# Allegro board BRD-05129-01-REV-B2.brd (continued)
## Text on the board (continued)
DISPLAY_BOTTOM: C369 | C557 | R462 | MH4 | MH3 | J13 | D | C | MH7 | B | 40 | 20 | 60 | U30 | A | 1 | J2 | U28 | R205 | C49 | J6 | J18 | MH10 | J19 | MH6 | J20 | J3 | MH2 | U61 | JA1 | R171 | R173 | R172 | R170 | C110 | C117 | C118 | R206 | C111 | C112 | JA2 | J1 | WATCHDOG OUT | MIO26 | DS1 | DS2 | DS3 | DS4 | DS5 | DS6 | DS7 | DS8 | J17 | SW1 | GND | R45 | J16 | 12V_IN | SW2 | PS_SRST_L | TP3 | C238 | C376 | 11 | 12 | Q5 | C323 | C324 | U41 | C207 | MH5 | TP1 | J12 | C204 | C578 | 2 | C437 | R349 | C275 | R498 | C397 | C396 | C436 | R256 | C577 | C53 | 15 | C303 | C295 | C298 | C296 | C317 | C74 | R62 | R57 | R63 | R61 | R58 | C299 | C291 | C292 | MH9 | R469 | R468 | X6 | C405 | C404 | X5 | C592 | C591 | C530 | C513 | C527 | C514 | U44 | C318 | C274 | C515 | R484 | C529 | C517 | R481 | R482 | R483 | X8 | X7 | C417 | C416 | U46 | MH8 | C546 | C544 | C547 | C545 | C556 | C147 | C166 | C153 | C163 | C159 | R113 | C157 | R461 | J22 | R126 | 59 | J24 | J23 | X10 | C146 | LED1 | DS9 | C156 | C145 | R120 | R108 | R119 | R107 | R118 | R106 | R102 | R125 | R116 | R104 | R105 | R117 | R121 | R109 | DS10 | LED2 | R378 | C481 | C478 | C463 | R397 | C486 | C475 | R402 | C476 | U80 | C472 | R396 | R79 | C427 | C425 | R326 | R380 | R389 | R381 | R390 | R385 | R394 | C465 | C424 | R393 | R384 | R392 | R383 | R391 | R382 | R379 | R401 | C482 | C477 | R330 | R331 | C94 | C426 | R327 | MH11 | MH1 | Q19 | U42 | D1 | J4 | C236 | C565 | C203 | TP39 | C235 | C234 | U82 | TP37 | TP38 | R135 | R133 | C379 | C206 | C377 | C205 | C374 | C372 | C276 | R274 | C370 | C277 | C398 | C394 | Q21 | C392 | C286 | C297 | C285 | R265 | C390 | R296 | C300 | C283 | C388 | C272 | C284 | C525 | C524 | C587 | C589 | C523 | C410 | C520 | C526 | C408 | C588 | C590 | C519 | C516 | C406 | C528 | C518 | C402 | C293 | R306 | C400 | C294 | C422 | C420 | C418 | C414 | R316 | C412 | C164 | C162 | C555 | C160 | C158 | C148 | C152 | C155 | C161 | C144 | C167 | C151 | C165 | U36 | R122 | C149 | R110 | C150 | C154 | C470 | C479 | C468 | R471 | C474 | R472 | C467 | C469 | C464 | C473 | R387 | C87 | L4 | C466 | C471 | C484 | C480 | C483 | L5 | C485 | C96 | C88 | J21 | R235 | J15 | C97 | C93 | MH12 | SOM240_1 | SOM240_2 | J10 | 39 | PCB EDGE | FAN HDR | SOM FPD | CC PS | SOM PL | CC PL | SOM LPD | UF1 | UF2 | PWR IN | PS ETH | SLVS-EC | PL ETH | JTAG | PMOD1 | RESET | FWUEN | 12V PWR | PMOD2 | PMOD3 | PMOD4 | SFP+ | JTAG/UART | RPI GPIO
PLACE_BOUND_BOTTOM: R | U168 | US | C | N | I | Z | E | D | A | 1 | 60 | 40 | 20 | O | G | E115289 | Electrical Safety | 10 | MET | RoHS | D3C386 | JA1 | JA2 | HF
User.8: JA1 | 14 | 1 | A1 | RoHS | U172 | A | 60 | AMD | D3C386 | DE | UL | U144 | D | C | B | 10 | C1767 | C1766 | JA2 | HF
User.10: CLOCK | REGULATOR | 5V0_IN | OSC | USB PHY AND HUB | GATE DRIVERS | MOTOR PHASE | MOTOR VOLTAGE | & CURRENT ADCs
User.11: USB PHY AND HUB | REGULATOR | 5V0_IN | CLOCK | OSC | GATE DRIVERS | & CURRENT ADCs | MOTOR PHASE | MOTOR VOLTAGE
User.13: R | C369 | C557 | R462 | MH4 | MH3 | J13 | D | C | MH7 | B | 40 | 20 | 60 | U30 | A | 1 | J2 | U28 | R205 | C49 | J6 | J18 | MH10 | J19 | MH6 | J20 | J3 | MH2 | U61 | JA1 | R171 | R173 | R172 | R170 | C110 | C117 | C118 | R206 | C111 | C112 | JA2 | J1 | WATCHDOG OUT | MIO26 | DS1 | DS2 | DS3 | DS4 | DS5 | DS6 | DS7 | DS8 | J17 | SW1 | GND | R45 | J16 | 12V_IN | SW2 | PS_SRST_L | TP3 | C238 | C376 | 11 | 12 | Q5 | C323 | C324 | U41 | C207 | MH5 | TP1 | J12 | C204 | C578 | 2 | C437 | R349 | C275 | R498 | C397 | C396 | C436 | R256 | C577 | C53 | 15 | C303 | C295 | C298 | C296 | C317 | C74 | R62 | R57 | R63 | R61 | R58 | C299 | C291 | C292 | MH9 | R469 | R468 | X6 | C405 | C404 | X5 | C592 | C591 | C530 | C513 | C527 | C514 | U44 | C318 | C274 | C515 | R484 | C529 | C517 | R481 | R482 | R483 | X8 | X7 | C417 | C416 | U46 | MH8 | C546 | C544 | C547 | C545 | C556 | C147 | C166 | C153 | C163 | C159 | R113 | C157 | R461 | J22 | R126 | 59 | J24 | J23 | X10 | C146 | LED1 | DS9 | C156 | C145 | R120 | R108 | R119 | R107 | R118 | R106 | R102 | R125 | R116 | R104 | R105 | R117 | R121 | R109 | DS10 | LED2 | R378 | C481 | C478 | C463 | R397 | C486 | C475 | R402 | C476 | U80 | C472 | R396 | R79 | C427 | C425 | R326 | R380 | R389 | R381 | R390 | R385 | R394 | C465 | C424 | R393 | R384 | R392 | R383 | R391 | R382 | R379 | R401 | C482 | C477 | R330 | R331 | C94 | C426 | R327 | MH11 | MH1 | Q19 | U42 | D1 | J4 | C236 | C565 | C203 | TP39 | C235 | C234 | U82 | TP37 | TP38 | R135 | R133 | C379 | C206 | C377 | C205 | C374 | C372 | C276 | R274 | C370 | C277 | C398 | C394 | Q21 | C392 | C286 | C297 | C285 | R265 | C390 | R296 | C300 | C283 | C388 | C272 | C284 | C525 | C524 | C587 | C589 | C523 | C410 | C520 | C526 | C408 | C588 | C590 | C519 | C516 | C406 | C528 | C518 | C402 | C293 | R306 | C400 | C294 | C422 | C420 | C418 | C414 | R316 | C412 | C164 | C162 | C555 | C160 | C158 | C148 | C152 | C155 | C161 | C144 | C167 | C151 | C165 | U36 | R122 | C149 | R110 | C150 | C154 | C470 | C479 | C468 | R471 | C474 | R472 | C467 | C469 | C464 | C473 | R387 | C87 | L4 | C466 | C471 | C484 | C480 | C483 | L5 | C485 | C96 | C88 | J21 | R235 | J15 | C97 | C93 | MH12 | SOM240_1 | SOM240_2 | J10 | 39 | PCB EDGE | FAN HDR | SOM FPD | CC PS | SOM PL | CC PL | SOM LPD | UF1 | UF2 | PWR IN | PS ETH | SLVS-EC | PL ETH | JTAG | PMOD1 | RESET | FWUEN | 12V PWR | PMOD2 | PMOD3 | PMOD4 | SFP+ | JTAG/UART | RPI GPIO | SILKSCREEN TOP | TOP SIDE | ARTWORK, ROHS COMPLIANT, SCK-KR-05101-01 | PCB #    128-05101-01  REV B01 | Designed by Xilinx | SHEET     OF 20 | LAYER: | CGN | DATE: | PHONE:879-4451 | XILINX DOC USE ONLY | REVISION: B01 | DATAPACK: aa | 12/06/2021
User.16: MADE IN XX | XXX-YYZZ | FAB HOUSE TO ADD NAME TO TOP SIDE HERE: | FAB HOUSE TO ADD YEAR TO TOP SIDE HERE: | FAB HOUSE TO ADD WEEKS TO TOP SIDE HERE: | MUST BE IN EXPOSED COPPER | MAKE SURE THAT IT DOES NOT SHORT OUT ANYTHING ON THE BOARD | "XX" = COUNTRY CODE PER ISO 3166 | FAB VENDOR TO ADD MADE IN "XX" | MAINTENANCE AGENCY TO TOP SIDE | HERE: | CROSSED IMPEDENCE CALL OUTS DO NOT EXIST INPROVIDED DATA. IGNORE THEM. | SE WIDTH | 5.1 MIL | 4.0 MIL | 50 OHMS | 4.3/5.6/4.3 MIL | 4.3/5.7/4.3 MIL | 90 OHM DIFF | DIFF WIDTH/SPACE/WIDTH | 100 OHM DIFF | 3.5/6.5/3.5 MIL | 3.6/6.4/3.6 MIL | 128-05129-01 | DATA PACK: aa | 20. IMPEDANCE LAYERS TO HAVE A TOL. OF +/-10%. | 14. 100% ELECTRICAL TEST REQUIRED FOR CONTINUITY. BOARD SHALL HAVE A | 11. FINISH: OSP PLATING. | 10. SOLDER MASK REGISTRATION TO BE WITHIN DIAMETRICAL TRUE POSITION OF + / - 0.002"WITH APPLICABLE | 15. ALL VIAS ACUTAL DRILL SIZE TO BE +.001/-.001 INCHES. | 17. DRILL SIZES LISTED IN LEGEND ARE CONSIDERED FINIHSED HOLE SIZES. | 12. SILKSCREEN USING WHITE RoHS COMPLIANT, HALOGEN FREE MATERIAL | 19. THE 37.4 MIL NPTH IS A DRILL ON PAD AND SHOULD MAINTAIN A +/- 1 MIL TOLERANCE (4 PLACES) | 13. VENDOR LOGO AND DATE CODE TO BE MARKED ON LAYER 1 TOPSIDE. | 16. ANY VIA WITH A FINISHED HOLE SIZE 12 MILS OR LESS MAY BE TREATED AS DRILL SIZE. | 18. ALL 7.1 MIL VIAS TO BE PLUGGED WITH SOLDERMASK. | 1. USE ARTWORK FROM JOB: 128-05129-01-REV-B2 | NOTES: (UNLESS OTHERWISE SPECIFIED) | THIS FAB SHOULD BE "RoHS COMPLIANT". | 2. PLEASE SEE INTENTIONAL SHORT LIST: 128-05129-01-REV-B2_SHORTLIST | 3. THERE SHOULD BE NO OPEN NETS ON THIS DESIGN. | 5. FABRICATE TO IPC-A-600, CURRENT REVISION | 6. BOARD SHALL MEET THE INSPECTION CRITERIA OF | 7. SEE STACKUP DIAGRAM BELOW FOR MATERIAL. GLASS TRANSITION TEMPERATURE MUST MEET OR | 8. APPLY SOLDER MASK OVER BARE COPPER (SMOBC) IAW. IPC-SM-840, BOTH SIDES, USING LPI, COLOR GREEN | 9. LPI SOLDER MASK SHOULD BE RoHS COMPLIANT, HALOGEN FREE MATERIAL | 4. ODB++ USED FOR FAB MUST BE VERIFIED AGAINST THE PROVIDED IPC356 NETLIST. COPPER SLIVERS THAT ARE | EXCEED THE TEMPERATURE EXHIBITED WITH HIGH TEMPERATURE PROCESSES ASSOCIATED WITH LEAD FREE ASSEMBLY. | LESS THAN 0.003" IN WIDTH BETWEEN ANTI-PAD TO PLANE EDGE, ANTI-PAD TO SPLIT PLANE AND ANTI-PAD TO | FINISHED HOLE TOL. +0/- DRILL SIZE. HOLE CAN BE PLATED SHUT. | 0.003" COPPER WIDTH MUST BE ADDRESSED AND APPROVED IN WRITING BY SUPPLIER. | HOLE/PAD. | BOTH SIDES DISTORTION OF SILKSCREEN IS ACCEPTABLE  OVER TRACES.  EPOXY INK ON SOLDER LANDS IS | UL-RATING OF 94V-0. UL SYMBOL AND RATING SHALL BE MARKED SOLDER SIDE IN SILKSCREEN. | NO VIOLATION AFTER THE REMOVAL OF SLIVERS. ANY REQUIREMENT FOR SLIVER REMOVAL ABOVE OR EQUAL TO THE | NOT ACCEPTABLE. CLIP SILKSCREEN ON TOP OF ANY PAD OR VIA. | ANTI-PAD MUST BE REMOVED FROM THE MANUFACTURING ARTWORK. A NETLIST COMPARISON MUST BE PASSED WITH | ALL SPECIFIED TRACE WIDTHS ARE FINISHED TRACE WIDTHS. | a- ACCEPTABILITY AS PER IPC-A-600 (LATEST REVISION) CLASS II | b- QUALIFICATION AND PERFORMANCE AS PER IPC-6012 (LATEST REVISION)  CLASS II. | 29. BAKE AT 225 DEGREES F FOR 4 HOURS TO REMOVE ANY MOISTURE AFTER FABRICATION. | 30. ALL VIA-DRILLS TO BE COMPLETELY FILLED. | 28. THIEVING: DO NOT ADD COPPER THIEVING ON TOP LAYER OR BOTTOM LAYER. | 21. FOR IMPEDANCE DETAILS REFER TABLE NO 1,2 IN FAB DRAWING. | 22. FOR DRILL DETAILS REFER TO DRILL TABLES | 23. PLEASE SEE PANEL DRAWING FOR PANEL LAYOUT AND ASSEMBLY RAILS. THE PANEL LAYOUT AND | 24. TABS TO BE ROUTED OUT AFTER ASSEMBLY. | 25. BOARDS MAY NEED TO BE BAKED AFTER FABRICATION DUE TO PLATING AND MATERIAL TYPE. | 26. COPPER PLATING THICKNESS 1.3 MILS MINIMUM | 27. REMOVE ALL UNUSED PADS FROM INTERNAL LAYERS. | PLANARIZED SMOOTH AND PLATED OVER ON SURFACE.  USE SanEi NON-CONDUCTIVE EPOXY OR | VIA-IN-PAD MUST INCLUDE WRAP REQUIREMENTS PER IPC 6012B. | EQUIVALENT FILL MATERIALS MINIMUM OF .0007 TO BE PLATED ON SURFACE. | RAILS. PLEASE CONTACT XILINX BEFORE CHANGING. | THIEVING PATTERN IS TO BE 30 MIL SQUARE PADS. 50 MIL SPACING. | THIEVING TO BE ADDED ON INTERNAL LAYERS TO ACHIEVE BALANCED COPPER DENSITY. | ASSEMBLY RAILS SHOULD NOT BE CHANGED.IF THERE IS A ISSUE WITH THE PANEL LAYOUT AND ASSEMBLY | BALANCE OF COPPER IN UPPER AND LOWER HALFS OF THE BOARD TO BE WITHIN 1 SQ. MILLI-METER. | MAINTAIN 60 MILS CLEARANCE TO COPPER FEATURE. PLEASE PROVIDE A COPPER DENSITY REPORT BEFORE FAB. | 128-05129-01-REV-B2 | FABRICATION DRAWING | PCB,ROHS COMPLIANT
User.17: LINEAR DIMENSIONS +/-.005 | DIMENSIONS ARE IN INCHES | 4 | 128-05129-01-REV-B1 | PCB ASSEMBLY | 128-05129-01 | DATA PACK: aa | NOTES: (UNLESS OTHERWISE SPECIFIED) | 3. REFERENCE SCHEMATIC (OR AVL) FOR BILL OF MATERIALS. | 4. INSTALL SHUNT AT J1 PINS 1-2 WHERE SHOWN. | 2. BAG AND TAG (OR MARK CONTAINER) WITH PART NUMBER. | 5. APPLY ADHESIVE BUMPERS, 4 PLACES CENTERED ON MH1, MH2, MH3 AND MH4 WHERE SHOWN BOTTOM SIDE. | 9. BAKE AT 225 DEGREES FOR 4 HOURS TO REMOVE ANY MOISTURE BEFORE ASSEMBLY. | 1. ASSEMBLE TO MEET INSPECTION CRITERIA OF | 6. APPLY SERIAL NUMBER LABEL ON BOTTOM SIDE WHERE SHOWN. REFER TO LABELLING DOCUMENT FOR DETAILS. | 7. ROUTE OUT ASSEMBLY TABS AFTER ASSEMBLY IS COMPLETE. | 8. FAB IS BOUND TO USE "SAC305" SOLDER PASTE FOR COMPONENT ASSEMBLY. | IPC-A-610, CLASS 2, CURRENT REVISION. | ENSURE BOARD EDGES ARE LEFT SMOOTH. | PRIMARY SIDE | SECONDARY SIDE
User.20: FIGURE | FINISHED_SIZE | 7.1 | 8.0 | 9.8 | 12.0 | 28.0 | 35.0 | 36.0 | 40.0 | 42.0 | 44.0 | 46.0 | 51.2 | 56.0 | 62.0 | 63.0 | 91.0 | 106.0 | 134.0 | 37.4 | 128.0 | 137.8 | DRILL CHART: TOP to BOTTOM | ALL UNITS ARE IN MILS | TOLERANCE_DRILL | +2.0/-2.0 | +3.0/-3.0 | PLATED | NON-PLATED | QTY | 221 | 149 | 2135 | 25 | 34 | 31 | 18 | 20 | 10 | 2 | 1 | 21 | 6 | 33 | 8 | 9 | 4 | 3 | 2766 | TOTAL HOLES:
User.21: FIGURE | FINISHED_SIZE | 10.0 | DRILL CHART: TOP to L03_SIG | ALL UNITS ARE IN MILS | TOLERANCE_DRILL | +2.0/-2.0 | PLATED | QTY | 191 | TOTAL HOLES:
User.22: LINEAR DIMENSIONS +/-.127 | DIMENSIONS ARE IN MM. | 128-05129-01 | DATA PACK: aa | 128-05129-01-REV-B1 | PCB,ROHS COMPLIANT | PANEL DRAWING
User.23: FIGURE | FINISHED_SIZE | 10.0 | DRILL CHART: L12_SIG to BOTTOM | ALL UNITS ARE IN MILS | TOLERANCE_DRILL | +2.0/-2.0 | PLATED | QTY | 40 | TOTAL HOLES:
User.24: MOTOR PC V | PL_5V0 | MOTOR PA C | MOTOR PC C | MOTOR PB C | MOTOR PB V | PL_12V0 | PL_4V5_TRQ | PL_1V8 | PL_3V3 | PS_ETH_0V9 | PL_2V5 | PS_1V8 | PS_1V2 | PS_3V3 | 12V_IN | A | PN 128-05129-01 REV A1 | MOTOR PA V | PL_ETH_0V9 | 5V0_IN | 12V_IN_JACK | UTIL_3V3 | RoHS
User.29: R651 | R622 | Q28 | TP60 | D16 | R672 | D23 | R642 | TP41 | D15 | U117 | D10 | R670 | TP42 | U136 | D6 | R669 | D18 | C618 | Q27 | U135 | C801 | D8 | C767 | C743 | R656 | R671 | C723 | R646 | TP44 | C802 | R648 | D13 | TP43 | R647 | C603 | R661 | D12 | R519 | C604 | R660 | C607 | C686 | C687 | R515 | R514 | C609 | R628 | C608 | C610 | R619 | C606 | R634 | C605 | C660 | R591 | L16 | C782 | C781 | R676 | R677 | R583 | C750 | R570 | R584 | R571 | C662 | R573 | R587 | R590 | R589 | R564 | R563 | C677 | R575 | R516 | R576 | C698 | C646 | TP40 | U99 | C704 | C748 | C689 | C654 | C678 | C661 | U119 | R566 | R565 | C669 | C705 | C653 | C663 | C651 | C652 | R728 | C619 | R528 | R526 | R719 | R711 | R727 | R712 | C665 | R58 | R720 | R61 | R754 | R562 | R480 | R478 | R479 | TP61 | C617 | C776 | R675 | R673 | C775 | C664 | Q26 | R715 | R707 | TP56 | R63 | R471 | R716 | U91 | R708 | R723 | TP59 | R724 | R64 | R685 | R27 | C27 | R501 | R477 | R507 | C787 | U122 | D21 | C304 | C300 | C296 | R539 | C291 | R219 | C29 | R706 | C786 | U125 | U137 | R680 | R753 | R752 | R741 | R744 | R749 | R745 | R218 | TP58 | C290 | R743 | R739 | R17 | R747 | R751 | U92 | C785 | R750 | R738 | R746 | R742 | R748 | R740 | U12 | C16 | C23 | R535 | R551 | X2 | C103 | C569 | U108 | U112 | U114 | C642 | R550 | C639 | U110 | U9 | C22 | C286 | R560 | Q29 | R23 | C568 | C298 | R221 | C303 | R523 | R757 | U100 | U24 | C284 | X13 | C295 | C754 | TP57 | U96 | C732 | C718 | U115 | X5 | C755 | TP54 | X12 | C90 | TP52 | X6 | U111 | U109 | C719 | C733 | R267 | R266 | U11 | C78 | U64 | R446 | U23 | R530 | R28 | C276 | R253 | R252 | R130 | R463 | U45 | C79 | R45 | R7 | C275 | R429 | C565 | C278 | C273 | U3 | R209 | C86 | R36 | R213 | C369 | C557 | R462 | C567 | R464 | U71 | X11 | R467 | C564 | R275 | U38 | C566 | C329 | C371 | C373 | C175 | R466 | R223 | U82 | C563 | L1 | C26 | R248 | R249 | TP51 | C25 | C24 | R21 | U5 | Z5 | R26 | R250 | R251 | R165 | R164 | R44 | R163 | R162 | R264 | C344 | C621 | C206 | R32 | C38 | TP65 | TP64 | TP63 | TP62 | U6 | R283 | R280 | R281 | R282 | R277 | R279 | R278 | Z1 | R31 | R263 | C354 | C353 | C234 | C30 | R276 | R39 | C208 | TP53 | C210 | C41 | R167 | D2 | L8 | R4 | C5 | Q17 | Q10 | Q8 | Q6 | Q7 | C50 | Q9 | Q23 | C209 | R38 | TP50 | R294 | R159 | R157 | R254 | R160 | R260 | R161 | R158 | C49 | R295 | C1 | C2 | L9 | C4 | C3 | U107 | U106 | Q25 | U113 | Q24 | U43 | U67 | U37 | U66 | Q18 | R755 | R533 | C765 | TP45 | R532 | R531 | R653 | C742 | R520 | R652 | R643 | R641 | C715 | C763 | C713 | C722 | C620 | D17 | R529 | R527 | C714 | TP46 | R650 | C601 | C734 | R518 | C764 | R517 | C731 | R683 | C759 | C747 | D19 | R649 | R663 | R681 | R534 | C758 | R572 | R662 | C598 | L11 | C694 | L13 | R574 | R623 | R568 | R627 | C600 | C650 | R633 | R585 | R618 | R586 | R620 | C599 | R588 | R582 | R617 | D20 | R569 | C658 | R626 | C648 | R632 | C779 | C649 | C647 | C655 | C659 | R674 | U118 | U128 | C774 | U130 | U134 | U132 | Q30 | R561 | U120 | R721 | R726 | R713 | R718 | R704 | R729 | R710 | R705 | R684 | U133 | U131 | U129 | U127 | C788 | R29 | U8 | R722 | R709 | R702 | R703 | C614 | TP55 | R725 | R714 | R717 | C28 | C615 | U26 | R6 | U97 | C299 | R220 | C14 | U123 | U124 | C289 | Z6 | R469 | C310 | C104 | R468 | C616 | C309 | Q19 | R268 | C316 | C292 | R472 | R262 | C315 | R500 | R222 | C297 | R243 | C17 | C283 | C612 | R522 | C21 | C282 | R24 | C613 | C280 | C611 | C281 | R521 | C279 | C91 | C102 | R210 | C312 | C277 | C7 | C80 | C81 | C8 | C75 | R66 | R241 | C548 | C44 | R41 | U22 | C355 | R452 | R451 | Z4 | R447 | R450 | R14 | R448 | R16 | U15 | R449 | U19 | C6 | C356 | R55 | TP48 | R56 | R428 | C35 | C33 | C319 | C32 | C37 | TP47 | R33 | C34 | R34 | C39 | C581 | R30 | R133 | C36 | C40 | R134 | C582 | C31 | TP49 | C42 | R495 | C43 | R1 | R473 | U89 | U14 | R166 | R5 | Q22 | R474 | C51 | U13 | R48 | U7 | R51 | C387 | R47 | R50 | R49 | R494 | R46 | C237 | U1 | Q20 | R261 | C52 | U105 | R759
User.35: FIGURE | FINISHED_SIZE | 33.0x26.0 | 59.0x32.0 | 66.9291x23.622 | 118.0x40.0 | 138.0x40.0 | SLOT HOLES: TOP to BOTTOM | ALL UNITS ARE IN MILS | TOLERANCE_DRILL | +3.0/-3.0 | +2.0/-2.0 | +4.0/-4.0 | PLATED | QTY | 2 | 1 | 9 | TOTAL HOLES:
